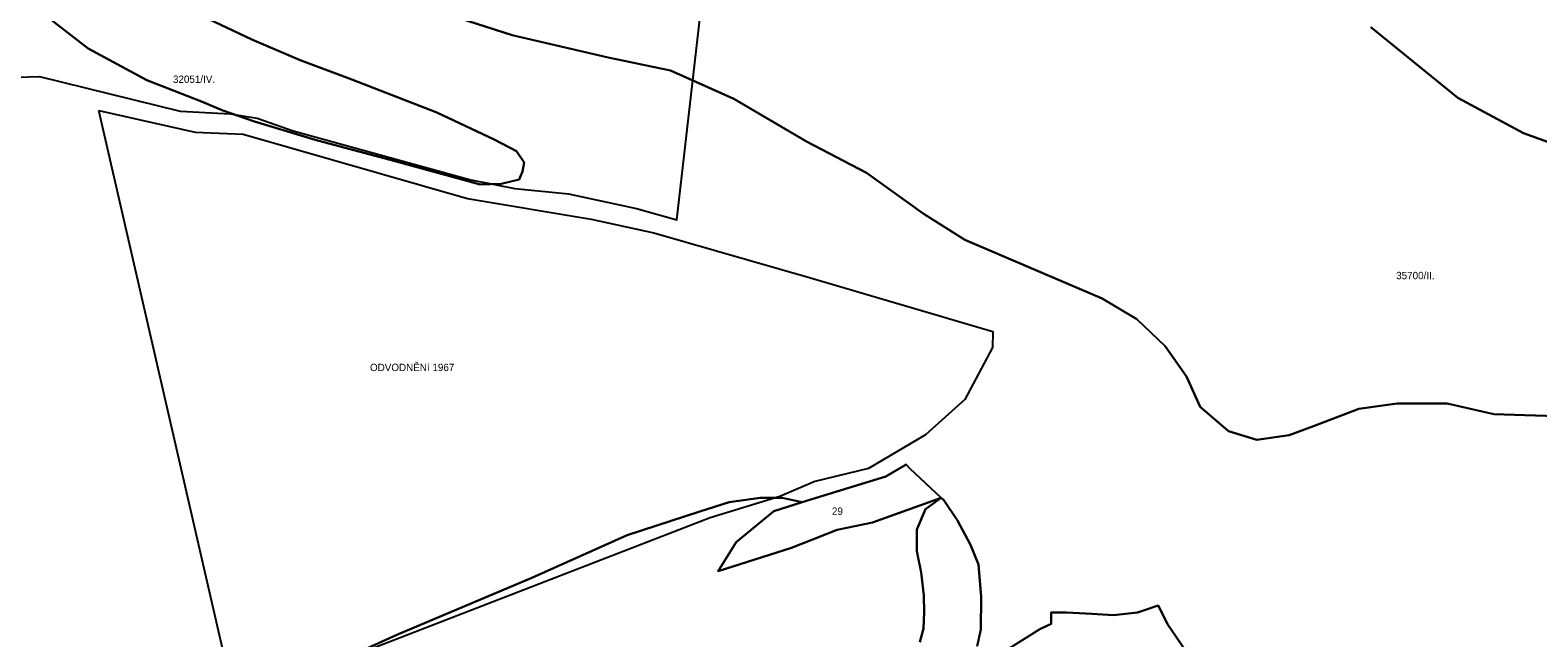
# Model space of a CAD drawing. Extents: x -521621 to -516761, y -1190184 to -1184927.
# Drawn here: x -520631 to -519813, y -1187439 to -1187109 of the extents above; entities that cross this region are included whole.
import ezdxf

# ---------------------------------------------------------------- set-up
doc = ezdxf.new("R2010")
doc.units = 0
doc.layers.add('BPEJ_s', color=7, linetype='Continuous')
doc.layers.add('odvodneni_s', color=7, linetype='Continuous')

msp = doc.modelspace()

# ---------------------------------------------------------------- linework, layer by layer
at = {"layer": 'BPEJ_s'}
for p, q in [((-520622.11, -1187101.65), (-520599.61, -1187118.9)), ((-520510.76, -1187114.03), (-520534.38, -1187102.77)), ((-520417.41, -1187096.39), (-520369.42, -1187111.77)), ((-520369.42, -1187111.77), (-520317.3, -1187123.78)), ((-520599.61, -1187118.9), (-520567.75, -1187136.16)), ((-520484.52, -1187125.28), (-520510.76, -1187114.03)), ((-520456.4, -1187135.78), (-520484.52, -1187125.28)), ((-520317.3, -1187123.78), (-520283.56, -1187130.91)), ((-520567.75, -1187136.16), (-520538.13, -1187147.79)), ((-520410.28, -1187153.79), (-520456.4, -1187135.78)), ((-520283.56, -1187130.91), (-520249.07, -1187146.29)), ((-520538.13, -1187147.79), (-520526.51, -1187152.67)), ((-520526.51, -1187152.67), (-520509.31, -1187158.58)), ((-520249.07, -1187146.29), (-520209.7, -1187169.55)), ((-520509.31, -1187158.58), (-520476.43, -1187168.49)), ((-520379.16, -1187168.42), (-520410.28, -1187153.79)), ((-520476.43, -1187168.49), (-520433.72, -1187180.03)), ((-520367.17, -1187174.8), (-520379.16, -1187168.42)), ((-520363.04, -1187180.8), (-520367.17, -1187174.8)), ((-520209.7, -1187169.55), (-520177.08, -1187186.43)), ((-520433.72, -1187180.03), (-520386.75, -1187192.85)), ((-520365.67, -1187190.18), (-520363.79, -1187185.68)), ((-520363.79, -1187185.68), (-520363.04, -1187180.8)), ((-520386.75, -1187192.85), (-520375.41, -1187192.43)), ((-520375.41, -1187192.43), (-520365.67, -1187190.18)), ((-520177.08, -1187186.43), (-520146.34, -1187208.56)), ((-520146.34, -1187208.56), (-520123.85, -1187222.82)), ((-520123.85, -1187222.82), (-520087.85, -1187238.2)), ((-520087.85, -1187238.2), (-520049.24, -1187254.71)), ((-520049.24, -1187254.71), (-520030.49, -1187265.96)), ((-520030.49, -1187265.96), (-520015.12, -1187280.59)), ((-520015.12, -1187280.59), (-520003.5, -1187297.1)), ((-520003.5, -1187297.1), (-519996, -1187313.6)), ((-519996, -1187313.6), (-519980.63, -1187326.73)), ((-519934.51, -1187324.11), (-519909.83, -1187314.7)), ((-519909.83, -1187314.7), (-519889.09, -1187311.73)), ((-519889.09, -1187311.73), (-519861.99, -1187311.73)), ((-519861.99, -1187311.73), (-519836.59, -1187317.66)), ((-519947.64, -1187328.98), (-519934.51, -1187324.11)), ((-519836.59, -1187317.66), (-519797.22, -1187318.93)), ((-519980.63, -1187326.73), (-519965.26, -1187331.61)), ((-519965.26, -1187331.61), (-519947.64, -1187328.98)), ((-520155.62, -1187344.86), (-520166.59, -1187351.48)), ((-520153.58, -1187347.14), (-520155.62, -1187344.86)), ((-520136.66, -1187362.99), (-520153.58, -1187347.14)), ((-520166.59, -1187351.48), (-520193.26, -1187359.52)), ((-520251.75, -1187365.32), (-520267.54, -1187370.4)), ((-520234.84, -1187363.07), (-520251.75, -1187365.32)), ((-520223, -1187363.07), (-520234.84, -1187363.07)), ((-520212.07, -1187365.41), (-520223, -1187363.07)), ((-520193.26, -1187359.52), (-520212.07, -1187365.41)), ((-520135.15, -1187364.29), (-520136.66, -1187362.99)), ((-520127.69, -1187375.36), (-520135.15, -1187364.29)), ((-520267.54, -1187370.4), (-520307, -1187383.37)), ((-520120.74, -1187388.64), (-520127.69, -1187375.36)), ((-520307, -1187383.37), (-520358.86, -1187406.5)), ((-520116.31, -1187399.18), (-520120.74, -1187388.64)), ((-520358.86, -1187406.5), (-520432.14, -1187437.52)), ((-520114.84, -1187416.89), (-520116.31, -1187399.18)), ((-520115.05, -1187434.6), (-520114.84, -1187416.89)), ((-520023.07, -1187422.95), (-520026.85, -1187424.2)), ((-520022.04, -1187422.61), (-520023.07, -1187422.95)), ((-520020.38, -1187422.06), (-520022.04, -1187422.61)), ((-520018.79, -1187421.54), (-520020.38, -1187422.06)), ((-520016.62, -1187425.68), (-520018.79, -1187421.54)), ((-520068.5, -1187425.26), (-520076.97, -1187425.26)), ((-520076.97, -1187425.26), (-520076.97, -1187431.47)), ((-520054.86, -1187426.09), (-520068.5, -1187425.26)), ((-520043.08, -1187426.71), (-520054.86, -1187426.09)), ((-520030.06, -1187425.26), (-520043.08, -1187426.71)), ((-520028.42, -1187424.72), (-520030.06, -1187425.26)), ((-520026.85, -1187424.2), (-520028.42, -1187424.72)), ((-520013.73, -1187431.67), (-520016.62, -1187425.68)), ((-520432.14, -1187437.52), (-520468.22, -1187453.88)), ((-520117.15, -1187443.67), (-520115.05, -1187434.6)), ((-520082.97, -1187434.36), (-520101.58, -1187446)), ((-520076.97, -1187431.47), (-520082.97, -1187434.36)), ((-520004.02, -1187445.95), (-520013.73, -1187431.67))]:
    msp.add_line(p, q, dxfattribs=at)
for points in [[(-520534.38, -1187102.77), (-520510.76, -1187114.03), (-520484.52, -1187125.28), (-520456.4, -1187135.78), (-520410.28, -1187153.79), (-520379.16, -1187168.42), (-520367.17, -1187174.8), (-520363.04, -1187180.8), (-520363.79, -1187185.68), (-520365.67, -1187190.18), (-520375.41, -1187192.43), (-520386.75, -1187192.85), (-520433.72, -1187180.03), (-520476.43, -1187168.49), (-520509.31, -1187158.58), (-520526.51, -1187152.67), (-520538.13, -1187147.79), (-520567.75, -1187136.16), (-520599.61, -1187118.9), (-520622.11, -1187101.65)], [(-519797.22, -1187318.93), (-519836.59, -1187317.66), (-519861.99, -1187311.73), (-519889.09, -1187311.73), (-519909.83, -1187314.7), (-519934.51, -1187324.11), (-519947.64, -1187328.98), (-519965.26, -1187331.61), (-519980.63, -1187326.73), (-519996, -1187313.6), (-520003.5, -1187297.1), (-520015.12, -1187280.59), (-520030.49, -1187265.96), (-520049.24, -1187254.71), (-520087.85, -1187238.2), (-520123.85, -1187222.82), (-520146.34, -1187208.56), (-520177.08, -1187186.43), (-520209.7, -1187169.55), (-520249.07, -1187146.29), (-520283.56, -1187130.91), (-520317.3, -1187123.78), (-520369.42, -1187111.77), (-520417.41, -1187096.39)], [(-519903.36, -1187107.38), (-519856.17, -1187145.7), (-519820.61, -1187164.86), (-519773.43, -1187181.96)], [(-519773.43, -1187181.96), (-519820.61, -1187164.86), (-519856.17, -1187145.7), (-519903.36, -1187107.38)], [(-520468.22, -1187453.88), (-520432.14, -1187437.52), (-520358.86, -1187406.5), (-520307, -1187383.37), (-520267.54, -1187370.4), (-520251.75, -1187365.32), (-520234.84, -1187363.07), (-520223, -1187363.07), (-520212.07, -1187365.41), (-520227.51, -1187370.25), (-520247.86, -1187387.06), (-520257.72, -1187402.79), (-520217.81, -1187390.15), (-520193, -1187380.43), (-520173.96, -1187376.44), (-520136.66, -1187362.99), (-520145.18, -1187369.24), (-520149.82, -1187380.21), (-520149.82, -1187392.01), (-520147.5, -1187403.61), (-520146.02, -1187416.05), (-520145.81, -1187425.12), (-520146.23, -1187433.97), (-520148.13, -1187441.35)], [(-520148.13, -1187441.35), (-520146.23, -1187433.97), (-520145.81, -1187425.12), (-520146.02, -1187416.05), (-520147.5, -1187403.61), (-520149.82, -1187392.01), (-520149.82, -1187380.21), (-520145.18, -1187369.24), (-520136.66, -1187362.99), (-520135.15, -1187364.29), (-520127.69, -1187375.36), (-520120.74, -1187388.64), (-520116.31, -1187399.18), (-520114.84, -1187416.89), (-520115.05, -1187434.6), (-520117.15, -1187443.67)], [(-520101.58, -1187446), (-520082.97, -1187434.36), (-520076.97, -1187431.47), (-520076.97, -1187425.26), (-520068.5, -1187425.26), (-520054.86, -1187426.09), (-520043.08, -1187426.71), (-520030.06, -1187425.26), (-520028.42, -1187424.72), (-520026.85, -1187424.2), (-520023.07, -1187422.95), (-520022.04, -1187422.61), (-520020.38, -1187422.06), (-520018.79, -1187421.54), (-520016.62, -1187425.68), (-520013.73, -1187431.67), (-520004.02, -1187445.95)]]:
    msp.add_lwpolyline(points, dxfattribs=at)
msp.add_lwpolyline([(-520212.07, -1187365.41), (-520193.26, -1187359.52), (-520166.59, -1187351.48), (-520155.62, -1187344.86), (-520153.58, -1187347.14), (-520136.66, -1187362.99), (-520173.96, -1187376.44), (-520193, -1187380.43), (-520217.81, -1187390.15), (-520257.72, -1187402.79), (-520247.86, -1187387.06), (-520227.51, -1187370.25)], close=True, dxfattribs=at)
at = {"layer": 'odvodneni_s'}
msp.add_lwpolyline([(-520696.62, -1187081.22), (-520712.14, -1187143.85), (-520676.24, -1187142.96), (-520637.97, -1187134.59), (-520626.08, -1187134.07), (-520549.68, -1187152.94), (-520522.41, -1187154.49), (-520507.8, -1187156.82), (-520488.41, -1187163.67), (-520391.84, -1187190.3), (-520367.93, -1187195.08), (-520338.85, -1187197.93), (-520302, -1187205.94), (-520280.02, -1187212.1), (-520239.28, -1186854.88)], dxfattribs=at)
msp.add_lwpolyline([(-520593.76, -1187152.58), (-520541.54, -1187164.45), (-520515.42, -1187165.48), (-520393.78, -1187200.38), (-520326.56, -1187211.63), (-520292.57, -1187219), (-520207.51, -1187243.56), (-520108.49, -1187272.64), (-520108.69, -1187281.29), (-520123.82, -1187309.68), (-520145.11, -1187328.82), (-520175.98, -1187347.03), (-520205.14, -1187354.13), (-520224.13, -1187362.31), (-520261.94, -1187373.88), (-520520.06, -1187473.85)], close=True, dxfattribs=at)

# ---------------------------------------------------------------- texts
at = {"layer": 'BPEJ_s'}
for s, p in [('32051/IV.', (-520553.59, -1187137.63)), ('35700/II.', (-519889.63, -1187244.27)), ('29', (-520195.91, -1187372.26))]:
    msp.add_text(s, height=4, dxfattribs=at).set_placement(p)
at = {"layer": 'odvodneni_s'}
msp.add_text('ODVODNĚNí 1967', height=4, dxfattribs=at).set_placement((-520446.63, -1187294.18))

doc.saveas('drawing.dxf')
